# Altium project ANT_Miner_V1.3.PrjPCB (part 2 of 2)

## Sheet HashUnit3.SchDoc: ANT_Miner_V1.3
size A2; Date: 2013/11/20; DrawnBy: Bitmain Technology; SheetNumber: 8; SheetTotal: 9
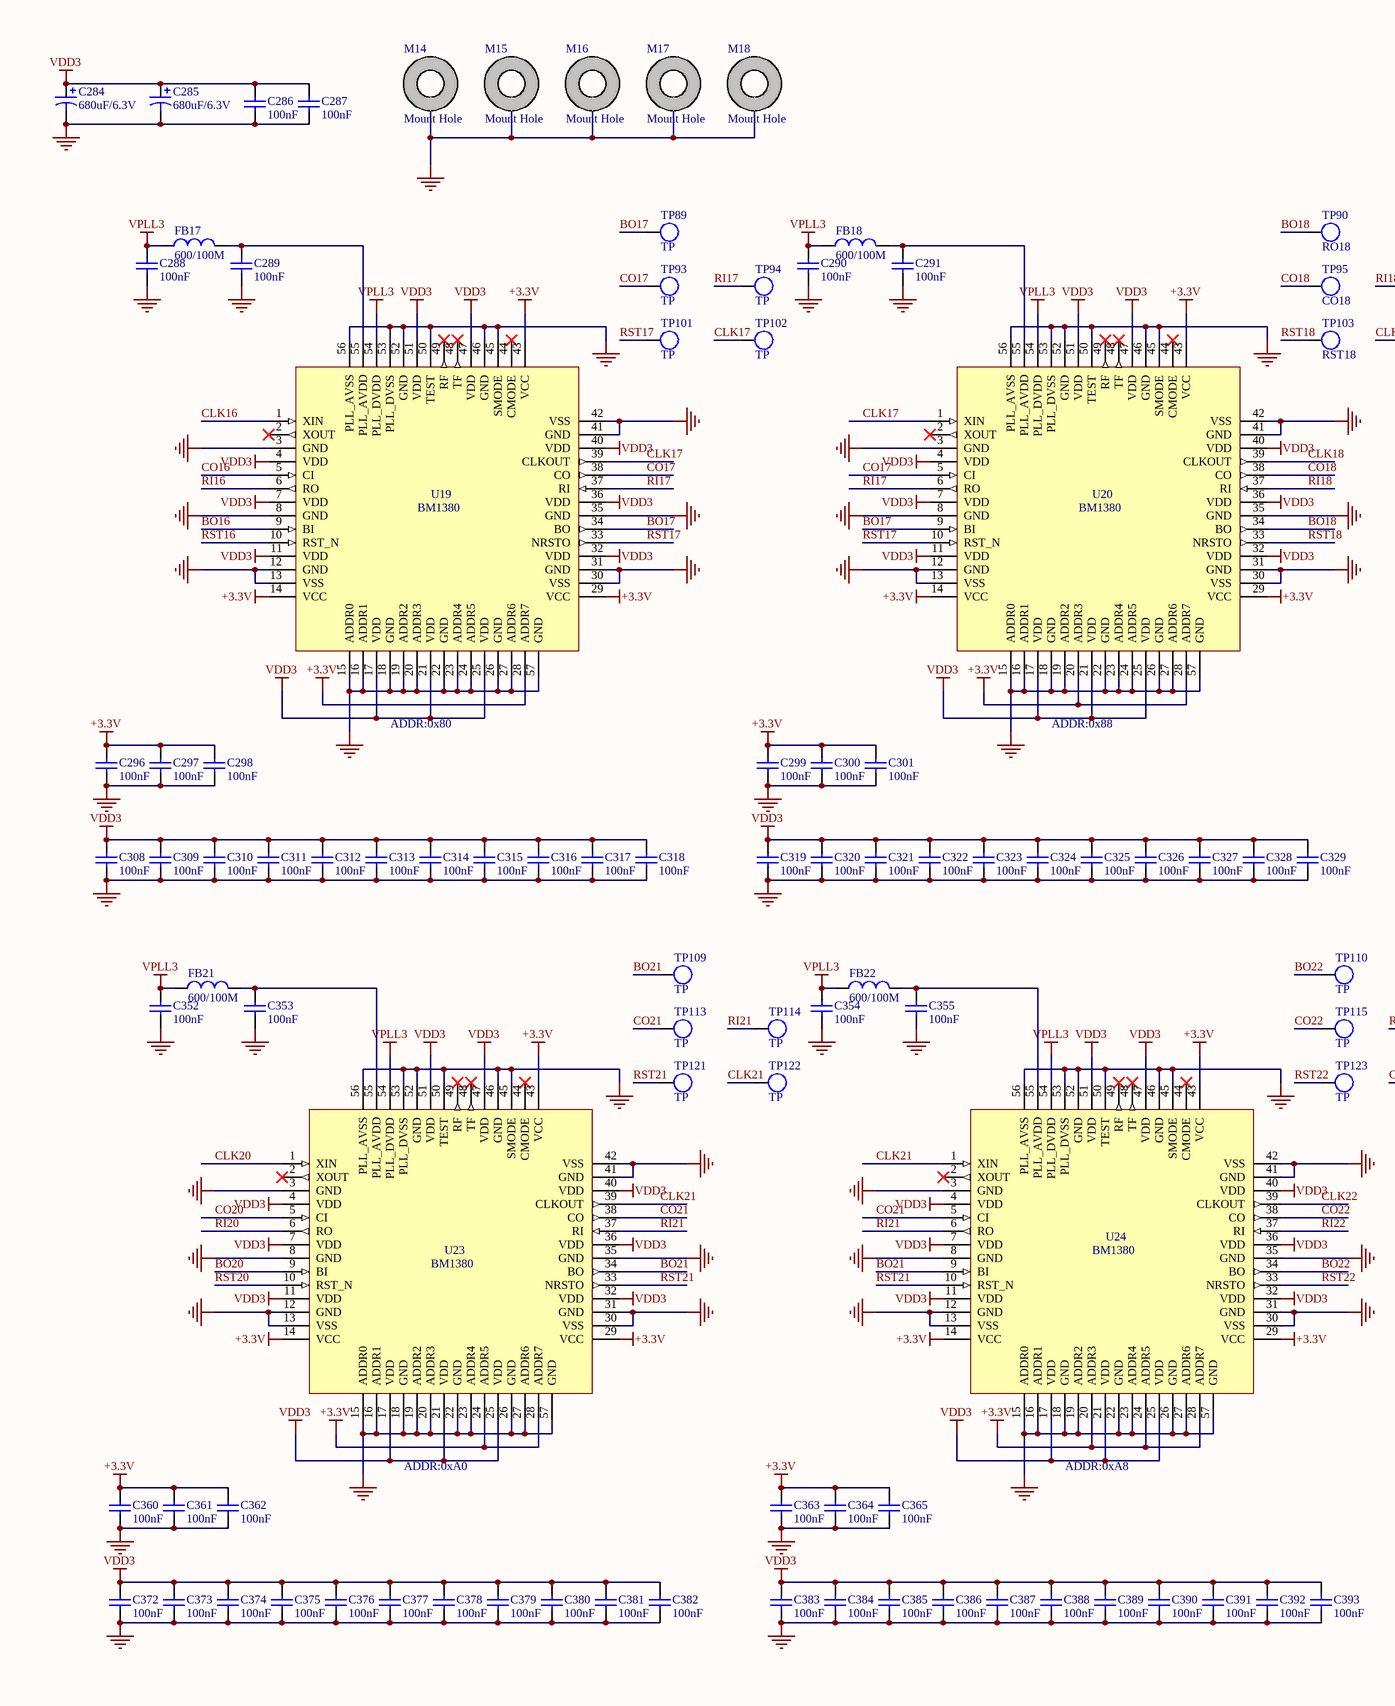
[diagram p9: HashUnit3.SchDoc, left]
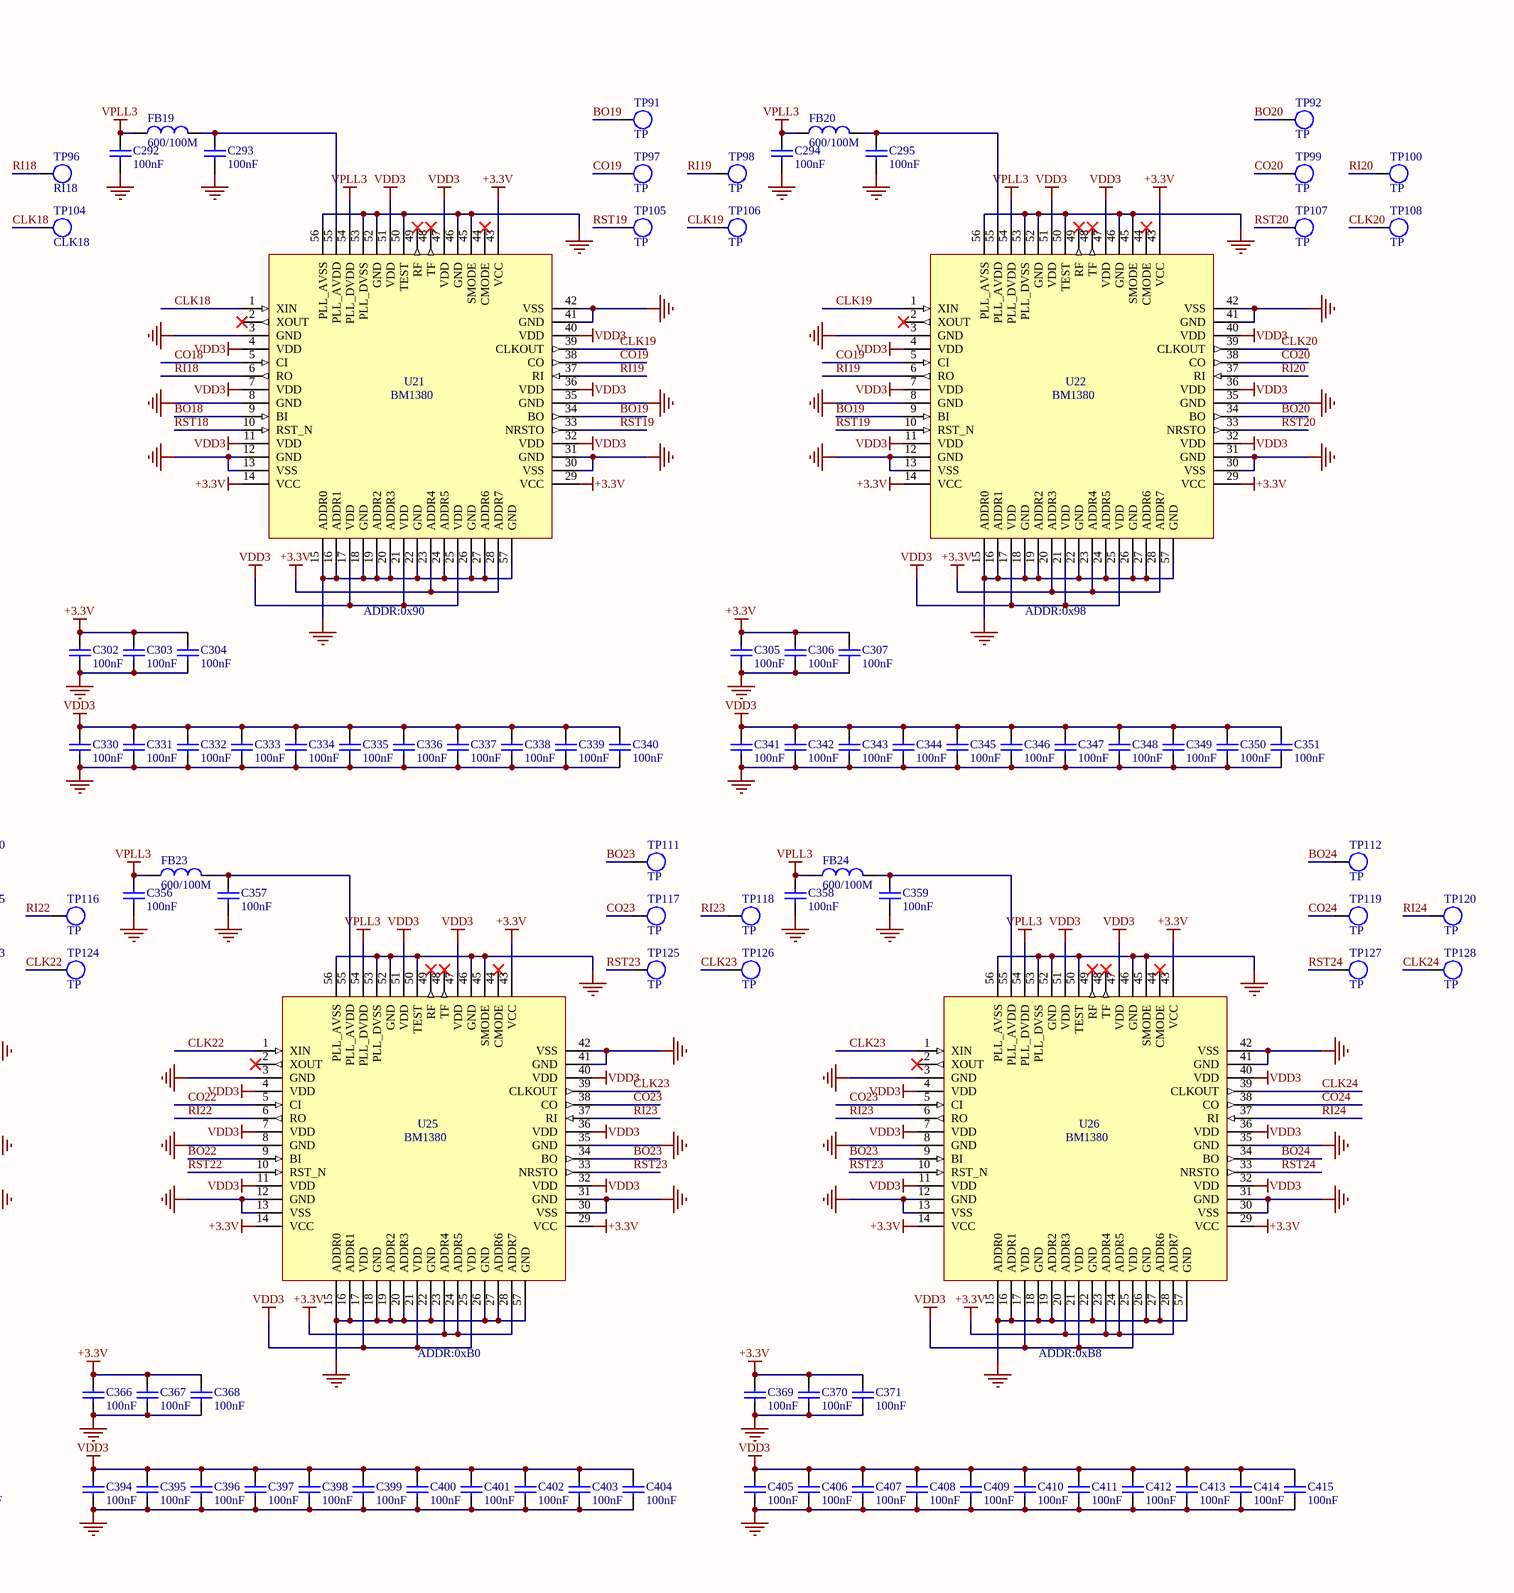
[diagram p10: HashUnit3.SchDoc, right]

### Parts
C284  680uF/6.3V  [D]
C285  680uF/6.3V  [D]
C286  100nF  [CC0603(1608)]
C287  100nF  [CC0603(1608)]
C288  100nF  [CC0603(1608)]
C289  100nF  [CC0603(1608)]
C290  100nF  [CC0603(1608)]
C291  100nF  [CC0603(1608)]
C292  100nF  [CC0603(1608)]
C293  100nF  [CC0603(1608)]
C294  100nF  [CC0603(1608)]
C295  100nF  [CC0603(1608)]
C296  100nF  [CC0603(1608)]
C297  100nF  [CC0603(1608)]
C298  100nF  [CC0603(1608)]
C299  100nF  [CC0603(1608)]
C300  100nF  [CC0603(1608)]
C301  100nF  [CC0603(1608)]
C302  100nF  [CC0603(1608)]
C303  100nF  [CC0603(1608)]
C304  100nF  [CC0603(1608)]
C305  100nF  [CC0603(1608)]
C306  100nF  [CC0603(1608)]
C307  100nF  [CC0603(1608)]
C308  100nF  [CC0603(1608)]
C309  100nF  [CC0603(1608)]
C310  100nF  [CC0603(1608)]
C311  100nF  [CC0603(1608)]
C312  100nF  [CC0603(1608)]
C313  100nF  [CC0603(1608)]
C314  100nF  [CC0603(1608)]
C315  100nF  [CC0603(1608)]
C316  100nF  [CC0603(1608)]
C317  100nF  [CC0603(1608)]
C318  100nF  [CC0603(1608)]
C319  100nF  [CC0603(1608)]
C320  100nF  [CC0603(1608)]
C321  100nF  [CC0603(1608)]
C322  100nF  [CC0603(1608)]
C323  100nF  [CC0603(1608)]
C324  100nF  [CC0603(1608)]
C325  100nF  [CC0603(1608)]
C326  100nF  [CC0603(1608)]
C327  100nF  [CC0603(1608)]
C328  100nF  [CC0603(1608)]
C329  100nF  [CC0603(1608)]
C330  100nF  [CC0603(1608)]
C331  100nF  [CC0603(1608)]
C332  100nF  [CC0603(1608)]
C333  100nF  [CC0603(1608)]
C334  100nF  [CC0603(1608)]
C335  100nF  [CC0603(1608)]
C336  100nF  [CC0603(1608)]
C337  100nF  [CC0603(1608)]
C338  100nF  [CC0603(1608)]
C339  100nF  [CC0603(1608)]
C340  100nF  [CC0603(1608)]
C341  100nF  [CC0603(1608)]
C342  100nF  [CC0603(1608)]
C343  100nF  [CC0603(1608)]
C344  100nF  [CC0603(1608)]
C345  100nF  [CC0603(1608)]
C346  100nF  [CC0603(1608)]
C347  100nF  [CC0603(1608)]
C348  100nF  [CC0603(1608)]
C349  100nF  [CC0603(1608)]
C350  100nF  [CC0603(1608)]
C351  100nF  [CC0603(1608)]
C352  100nF  [CC0603(1608)]
C353  100nF  [CC0603(1608)]
C354  100nF  [CC0603(1608)]
C355  100nF  [CC0603(1608)]
C356  100nF  [CC0603(1608)]
C357  100nF  [CC0603(1608)]
C358  100nF  [CC0603(1608)]
C359  100nF  [CC0603(1608)]
C360  100nF  [CC0603(1608)]
C361  100nF  [CC0603(1608)]
C362  100nF  [CC0603(1608)]
C363  100nF  [CC0603(1608)]
C364  100nF  [CC0603(1608)]
C365  100nF  [CC0603(1608)]
C366  100nF  [CC0603(1608)]
C367  100nF  [CC0603(1608)]
C368  100nF  [CC0603(1608)]
C369  100nF  [CC0603(1608)]
C370  100nF  [CC0603(1608)]
C371  100nF  [CC0603(1608)]
C372  100nF  [CC0603(1608)]
C373  100nF  [CC0603(1608)]
C374  100nF  [CC0603(1608)]
C375  100nF  [CC0603(1608)]
C376  100nF  [CC0603(1608)]
C377  100nF  [CC0603(1608)]
C378  100nF  [CC0603(1608)]
C379  100nF  [CC0603(1608)]
C380  100nF  [CC0603(1608)]
C381  100nF  [CC0603(1608)]
C382  100nF  [CC0603(1608)]
C383  100nF  [CC0603(1608)]
C384  100nF  [CC0603(1608)]
C385  100nF  [CC0603(1608)]
C386  100nF  [CC0603(1608)]
C387  100nF  [CC0603(1608)]
C388  100nF  [CC0603(1608)]
C389  100nF  [CC0603(1608)]
C390  100nF  [CC0603(1608)]
C391  100nF  [CC0603(1608)]
C392  100nF  [CC0603(1608)]
C393  100nF  [CC0603(1608)]
C394  100nF  [CC0603(1608)]
C395  100nF  [CC0603(1608)]
C396  100nF  [CC0603(1608)]
C397  100nF  [CC0603(1608)]
C398  100nF  [CC0603(1608)]
C399  100nF  [CC0603(1608)]
C400  100nF  [CC0603(1608)]
C401  100nF  [CC0603(1608)]
C402  100nF  [CC0603(1608)]
C403  100nF  [CC0603(1608)]
C404  100nF  [CC0603(1608)]
C405  100nF  [CC0603(1608)]
C406  100nF  [CC0603(1608)]
C407  100nF  [CC0603(1608)]
C408  100nF  [CC0603(1608)]
C409  100nF  [CC0603(1608)]
C410  100nF  [CC0603(1608)]
C411  100nF  [CC0603(1608)]
C412  100nF  [CC0603(1608)]
C413  100nF  [CC0603(1608)]
C414  100nF  [CC0603(1608)]
C415  100nF  [CC0603(1608)]
FB17  600/100M  [FB0603(1608)]
FB18  600/100M  [FB0603(1608)]
FB19  600/100M  [FB0603(1608)]
FB20  600/100M  [FB0603(1608)]
FB21  600/100M  [FB0603(1608)]
FB22  600/100M  [FB0603(1608)]
FB23  600/100M  [FB0603(1608)]
FB24  600/100M  [FB0603(1608)]
M14  Mount Hole  [MHOLE2]
M15  Mount Hole  [MHOLE2]
M16  Mount Hole  [MHOLE2]
M17  Mount Hole  [MHOLE2]
M18  Mount Hole  [MHOLE2]
TP89  TP  [TP_SMD]
TP90  value RO18  [TP_SMD]  (hidden comment: TP)
TP91  TP  [TP_SMD]
TP92  TP  [TP_SMD]
TP93  TP  [TP_SMD]
TP94  TP  [TP_SMD]
TP95  value CO18  [TP_SMD]  (hidden comment: TP)
TP96  value RI18  [TP_SMD]  (hidden comment: TP)
TP97  TP  [TP_SMD]
TP98  TP  [TP_SMD]
TP99  TP  [TP_SMD]
TP100  TP  [TP_SMD]
TP101  TP  [TP_SMD]
TP102  TP  [TP_SMD]
TP103  value RST18  [TP_SMD]  (hidden comment: TP)
TP104  value CLK18  [TP_SMD]  (hidden comment: TP)
TP105  TP  [TP_SMD]
TP106  TP  [TP_SMD]
TP107  TP  [TP_SMD]
TP108  TP  [TP_SMD]
TP109  TP  [TP_SMD]
TP110  TP  [TP_SMD]
TP111  TP  [TP_SMD]
TP112  TP  [TP_SMD]
TP113  TP  [TP_SMD]
TP114  TP  [TP_SMD]
TP115  TP  [TP_SMD]
TP116  TP  [TP_SMD]
TP117  TP  [TP_SMD]
TP118  TP  [TP_SMD]
TP119  TP  [TP_SMD]
TP120  TP  [TP_SMD]
TP121  TP  [TP_SMD]
TP122  TP  [TP_SMD]
TP123  TP  [TP_SMD]
TP124  TP  [TP_SMD]
TP125  TP  [TP_SMD]
TP126  TP  [TP_SMD]
TP127  TP  [TP_SMD]
TP128  TP  [TP_SMD]
U19  BM1380  [QFN56]
U20  BM1380  [QFN56]
U21  BM1380  [QFN56]
U22  BM1380  [QFN56]
U23  BM1380  [QFN56]
U24  BM1380  [QFN56]
U25  BM1380  [QFN56]
U26  BM1380  [QFN56]

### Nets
+3.3V: C296.2 C297.2 C298.2 C299.2 C300.2 C301.2 C302.2 C303.2 C304.2 C305.2 C306.2 C307.2 C360.2 C361.2 C362.2 C363.2 C364.2 C365.2 C366.2 C367.2 C368.2 C369.2 C370.2 C371.2 U19.14(VCC) U19.28(ADDR7) U19.29(VCC) U19.43(VCC) U20.14(VCC) U20.20(ADDR3) U20.28(ADDR7) U20.29(VCC) U20.43(VCC) U21.14(VCC) U21.23(ADDR4) U21.28(ADDR7) U21.29(VCC) U21.43(VCC) U22.14(VCC) U22.20(ADDR3) U22.23(ADDR4) U22.28(ADDR7) U22.29(VCC) U22.43(VCC) U23.14(VCC) U23.24(ADDR5) U23.28(ADDR7) U23.29(VCC) U23.43(VCC) U24.14(VCC) U24.20(ADDR3) U24.24(ADDR5) U24.28(ADDR7) U24.29(VCC) U24.43(VCC) U25.14(VCC) U25.23(ADDR4) U25.24(ADDR5) U25.28(ADDR7) U25.29(VCC) U25.43(VCC) U26.14(VCC) U26.20(ADDR3) U26.23(ADDR4) U26.24(ADDR5) U26.28(ADDR7) U26.29(VCC) U26.43(VCC)
GND: C284.2 C285.2 C286.1 C287.1 C288.2 C289.1 C290.2 C291.1 C292.2 C293.1 C294.2 C295.1 C296.1 C297.1 C298.1 C299.1 C300.1 C301.1 C302.1 C303.1 C304.1 C305.1 C306.1 C307.1 C308.1 C309.1 C310.1 C311.1 C312.1 C313.1 C314.1 C315.1 C316.1 C317.1 C318.1 C319.1 C320.1 C321.1 C322.1 C323.1 C324.1 C325.1 C326.1 C327.1 C328.1 C329.1 C330.1 C331.1 C332.1 C333.1 C334.1 C335.1 C336.1 C337.1 C338.1 C339.1 C340.1 C341.1 C342.1 C343.1 C344.1 C345.1 C346.1 C347.1 C348.1 C349.1 C350.1 C351.1 C352.2 C353.1 C354.2 C355.1 C356.2 C357.1 C358.2 C359.1 C360.1 C361.1 C362.1 C363.1 C364.1 C365.1 C366.1 C367.1 C368.1 C369.1 C370.1 C371.1 C372.1 C373.1 C374.1 C375.1 C376.1 C377.1 C378.1 C379.1 C380.1 C381.1 C382.1 C383.1 C384.1 C385.1 C386.1 C387.1 C388.1 C389.1 C390.1 C391.1 C392.1 C393.1 C394.1 C395.1 C396.1 C397.1 C398.1 C399.1 C400.1 C401.1 C402.1 C403.1 C404.1 C405.1 C406.1 C407.1 C408.1 C409.1 C410.1 C411.1 C412.1 C413.1 C414.1 C415.1 M14.0(PIN) M15.0(PIN) M16.0(PIN) M17.0(PIN) M18.0(PIN) U19.3(GND) U19.8(GND) U19.12(GND) U19.13(VSS) U19.15(ADDR0) U19.16(ADDR1) U19.18(GND) U19.19(ADDR2) U19.20(ADDR3) U19.22(GND) U19.23(ADDR4) U19.24(ADDR5) U19.26(GND) U19.27(ADDR6) U19.30(VSS) U19.31(GND) U19.35(GND) U19.41(GND) U19.42(VSS) U19.45(SMODE) U19.46(GND) U19.50(TEST) U19.52(GND) U19.53(PLL_DVSS) U19.56(PLL_AVSS) U19.57(GND) U20.3(GND) U20.8(GND) U20.12(GND) U20.13(VSS) U20.15(ADDR0) U20.16(ADDR1) U20.18(GND) U20.19(ADDR2) U20.22(GND) U20.23(ADDR4) U20.24(ADDR5) U20.26(GND) U20.27(ADDR6) U20.30(VSS) U20.31(GND) U20.35(GND) U20.41(GND) U20.42(VSS) U20.45(SMODE) U20.46(GND) U20.50(TEST) U20.52(GND) U20.53(PLL_DVSS) U20.56(PLL_AVSS) U20.57(GND) U21.3(GND) U21.8(GND) U21.12(GND) U21.13(VSS) U21.15(ADDR0) U21.16(ADDR1) U21.18(GND) U21.19(ADDR2) U21.20(ADDR3) U21.22(GND) U21.24(ADDR5) U21.26(GND) U21.27(ADDR6) U21.30(VSS) U21.31(GND) U21.35(GND) U21.41(GND) U21.42(VSS) U21.45(SMODE) U21.46(GND) U21.50(TEST) U21.52(GND) U21.53(PLL_DVSS) U21.56(PLL_AVSS) U21.57(GND) U22.3(GND) U22.8(GND) U22.12(GND) U22.13(VSS) U22.15(ADDR0) U22.16(ADDR1) U22.18(GND) U22.19(ADDR2) U22.22(GND) U22.24(ADDR5) U22.26(GND) U22.27(ADDR6) U22.30(VSS) U22.31(GND) U22.35(GND) U22.41(GND) U22.42(VSS) U22.45(SMODE) U22.46(GND) U22.50(TEST) U22.52(GND) U22.53(PLL_DVSS) U22.56(PLL_AVSS) U22.57(GND) U23.3(GND) U23.8(GND) U23.12(GND) U23.13(VSS) U23.15(ADDR0) U23.16(ADDR1) U23.18(GND) U23.19(ADDR2) U23.20(ADDR3) U23.22(GND) U23.23(ADDR4) U23.26(GND) U23.27(ADDR6) U23.30(VSS) U23.31(GND) U23.35(GND) U23.41(GND) U23.42(VSS) U23.45(SMODE) U23.46(GND) U23.50(TEST) U23.52(GND) U23.53(PLL_DVSS) U23.56(PLL_AVSS) U23.57(GND) U24.3(GND) U24.8(GND) U24.12(GND) U24.13(VSS) U24.15(ADDR0) U24.16(ADDR1) U24.18(GND) U24.19(ADDR2) U24.22(GND) U24.23(ADDR4) U24.26(GND) U24.27(ADDR6) U24.30(VSS) U24.31(GND) U24.35(GND) U24.41(GND) U24.42(VSS) U24.45(SMODE) U24.46(GND) U24.50(TEST) U24.52(GND) U24.53(PLL_DVSS) U24.56(PLL_AVSS) U24.57(GND) U25.3(GND) U25.8(GND) U25.12(GND) U25.13(VSS) U25.15(ADDR0) U25.16(ADDR1) U25.18(GND) U25.19(ADDR2) U25.20(ADDR3) U25.22(GND) U25.26(GND) U25.27(ADDR6) U25.30(VSS) U25.31(GND) U25.35(GND) U25.41(GND) U25.42(VSS) U25.45(SMODE) U25.46(GND) U25.50(TEST) U25.52(GND) U25.53(PLL_DVSS) U25.56(PLL_AVSS) U25.57(GND) U26.3(GND) U26.8(GND) U26.12(GND) U26.13(VSS) U26.15(ADDR0) U26.16(ADDR1) U26.18(GND) U26.19(ADDR2) U26.22(GND) U26.26(GND) U26.27(ADDR6) U26.30(VSS) U26.31(GND) U26.35(GND) U26.41(GND) U26.42(VSS) U26.45(SMODE) U26.46(GND) U26.50(TEST) U26.52(GND) U26.53(PLL_DVSS) U26.56(PLL_AVSS) U26.57(GND)
VDD3: C284.1 C285.1 C286.2 C287.2 C308.2 C309.2 C310.2 C311.2 C312.2 C313.2 C314.2 C315.2 C316.2 C317.2 C318.2 C319.2 C320.2 C321.2 C322.2 C323.2 C324.2 C325.2 C326.2 C327.2 C328.2 C329.2 C330.2 C331.2 C332.2 C333.2 C334.2 C335.2 C336.2 C337.2 C338.2 C339.2 C340.2 C341.2 C342.2 C343.2 C344.2 C345.2 C346.2 C347.2 C348.2 C349.2 C350.2 C351.2 C372.2 C373.2 C374.2 C375.2 C376.2 C377.2 C378.2 C379.2 C380.2 C381.2 C382.2 C383.2 C384.2 C385.2 C386.2 C387.2 C388.2 C389.2 C390.2 C391.2 C392.2 C393.2 C394.2 C395.2 C396.2 C397.2 C398.2 C399.2 C400.2 C401.2 C402.2 C403.2 C404.2 C405.2 C406.2 C407.2 C408.2 C409.2 C410.2 C411.2 C412.2 C413.2 C414.2 C415.2 U19.4(VDD) U19.7(VDD) U19.11(VDD) U19.17(VDD) U19.21(VDD) U19.25(VDD) U19.32(VDD) U19.36(VDD) U19.40(VDD) U19.47(VDD) U19.51(VDD) U20.4(VDD) U20.7(VDD) U20.11(VDD) U20.17(VDD) U20.21(VDD) U20.25(VDD) U20.32(VDD) U20.36(VDD) U20.40(VDD) U20.47(VDD) U20.51(VDD) U21.4(VDD) U21.7(VDD) U21.11(VDD) U21.17(VDD) U21.21(VDD) U21.25(VDD) U21.32(VDD) U21.36(VDD) U21.40(VDD) U21.47(VDD) U21.51(VDD) U22.4(VDD) U22.7(VDD) U22.11(VDD) U22.17(VDD) U22.21(VDD) U22.25(VDD) U22.32(VDD) U22.36(VDD) U22.40(VDD) U22.47(VDD) U22.51(VDD) U23.4(VDD) U23.7(VDD) U23.11(VDD) U23.17(VDD) U23.21(VDD) U23.25(VDD) U23.32(VDD) U23.36(VDD) U23.40(VDD) U23.47(VDD) U23.51(VDD) U24.4(VDD) U24.7(VDD) U24.11(VDD) U24.17(VDD) U24.21(VDD) U24.25(VDD) U24.32(VDD) U24.36(VDD) U24.40(VDD) U24.47(VDD) U24.51(VDD) U25.4(VDD) U25.7(VDD) U25.11(VDD) U25.17(VDD) U25.21(VDD) U25.25(VDD) U25.32(VDD) U25.36(VDD) U25.40(VDD) U25.47(VDD) U25.51(VDD) U26.4(VDD) U26.7(VDD) U26.11(VDD) U26.17(VDD) U26.21(VDD) U26.25(VDD) U26.32(VDD) U26.36(VDD) U26.40(VDD) U26.47(VDD) U26.51(VDD)
VPLL3: C288.1 C290.1 C292.1 C294.1 C352.1 C354.1 C356.1 C358.1 FB17.2 FB18.2 FB19.2 FB20.2 FB21.2 FB22.2 FB23.2 FB24.2 U19.54(PLL_DVDD) U20.54(PLL_DVDD) U21.54(PLL_DVDD) U22.54(PLL_DVDD) U23.54(PLL_DVDD) U24.54(PLL_DVDD) U25.54(PLL_DVDD) U26.54(PLL_DVDD)
BO16: U19.9(BI)
BO17: TP89.1 U19.34(BO) U20.9(BI)
BO18: TP90.1 U20.34(BO) U21.9(BI)
BO19: TP91.1 U21.34(BO) U22.9(BI)
BO20: TP92.1 U22.34(BO) U23.9(BI)
BO21: TP109.1 U23.34(BO) U24.9(BI)
BO22: TP110.1 U24.34(BO) U25.9(BI)
BO23: TP111.1 U25.34(BO) U26.9(BI)
BO24: TP112.1 U26.34(BO)
CLK16: U19.1(XIN)
CLK17: TP102.1 U19.39(CLKOUT) U20.1(XIN)
CLK18: TP104.1 U20.39(CLKOUT) U21.1(XIN)
CLK19: TP106.1 U21.39(CLKOUT) U22.1(XIN)
CLK20: TP108.1 U22.39(CLKOUT) U23.1(XIN)
CLK21: TP122.1 U23.39(CLKOUT) U24.1(XIN)
CLK22: TP124.1 U24.39(CLKOUT) U25.1(XIN)
CLK23: TP126.1 U25.39(CLKOUT) U26.1(XIN)
CLK24: TP128.1 U26.39(CLKOUT)
CO16: U19.5(CI)
CO17: TP93.1 U19.38(CO) U20.5(CI)
CO18: TP95.1 U20.38(CO) U21.5(CI)
CO19: TP97.1 U21.38(CO) U22.5(CI)
CO20: TP99.1 U22.38(CO) U23.5(CI)
CO21: TP113.1 U23.38(CO) U24.5(CI)
CO22: TP115.1 U24.38(CO) U25.5(CI)
CO23: TP117.1 U25.38(CO) U26.5(CI)
CO24: TP119.1 U26.38(CO)
RI16: U19.6(RO)
RI17: TP94.1 U19.37(RI) U20.6(RO)
RI18: TP96.1 U20.37(RI) U21.6(RO)
RI19: TP98.1 U21.37(RI) U22.6(RO)
RI20: TP100.1 U22.37(RI) U23.6(RO)
RI21: TP114.1 U23.37(RI) U24.6(RO)
RI22: TP116.1 U24.37(RI) U25.6(RO)
RI23: TP118.1 U25.37(RI) U26.6(RO)
RI24: TP120.1 U26.37(RI)
RST16: U19.10(RST_N)
RST17: TP101.1 U19.33(NRSTO) U20.10(RST_N)
RST18: TP103.1 U20.33(NRSTO) U21.10(RST_N)
RST19: TP105.1 U21.33(NRSTO) U22.10(RST_N)
RST20: TP107.1 U22.33(NRSTO) U23.10(RST_N)
RST21: TP121.1 U23.33(NRSTO) U24.10(RST_N)
RST22: TP123.1 U24.33(NRSTO) U25.10(RST_N)
RST23: TP125.1 U25.33(NRSTO) U26.10(RST_N)
RST24: TP127.1 U26.33(NRSTO)
NetC289_2: C289.2 FB17.1 U19.55(PLL_AVDD)
NetC291_2: C291.2 FB18.1 U20.55(PLL_AVDD)
NetC293_2: C293.2 FB19.1 U21.55(PLL_AVDD)
NetC295_2: C295.2 FB20.1 U22.55(PLL_AVDD)
NetC353_2: C353.2 FB21.1 U23.55(PLL_AVDD)
NetC355_2: C355.2 FB22.1 U24.55(PLL_AVDD)
NetC357_2: C357.2 FB23.1 U25.55(PLL_AVDD)
NetC359_2: C359.2 FB24.1 U26.55(PLL_AVDD)

Not connected (* = marked no-connect by the designer): U19 2(XOUT)* 44(CMODE)* 48(TF)* 49(RF)*; U20 2(XOUT)* 44(CMODE)* 48(TF)* 49(RF)*; U21 2(XOUT)* 44(CMODE)* 48(TF)* 49(RF)*; U22 2(XOUT)* 44(CMODE)* 48(TF)* 49(RF)*; U23 2(XOUT)* 44(CMODE)* 48(TF)* 49(RF)*; U24 2(XOUT)* 44(CMODE)* 48(TF)* 49(RF)*; U25 2(XOUT)* 44(CMODE)* 48(TF)* 49(RF)*; U26 2(XOUT)* 44(CMODE)* 48(TF)* 49(RF)*

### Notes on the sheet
- ADDR:0x80
- ADDR:0x88
- ADDR:0x90
- ADDR:0x98
- ADDR:0xA0
- ADDR:0xA8
- ADDR:0xB0
- ADDR:0xB8

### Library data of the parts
C284 C285 = T492C: Solid Tantalum Chip Capacitor, T492 Series - CWR11 Style Per Mil-PRF-55365/8
C286 C287 = Cap Semi: Capacitor (Semiconductor SIM Model)
C288-C415 = Cap: Capacitor
FB17-FB24 = FB: Inductor; Code_IEC: 1005
M14-M18 = M_Hole
TP89-TP128 = TP: Test Point

## Sheet HashUnit4.SchDoc: ANT_Miner_V1.3
size A2; Date: 2013/11/20; DrawnBy: Bitmain Technology; SheetNumber: 9; SheetTotal: 9
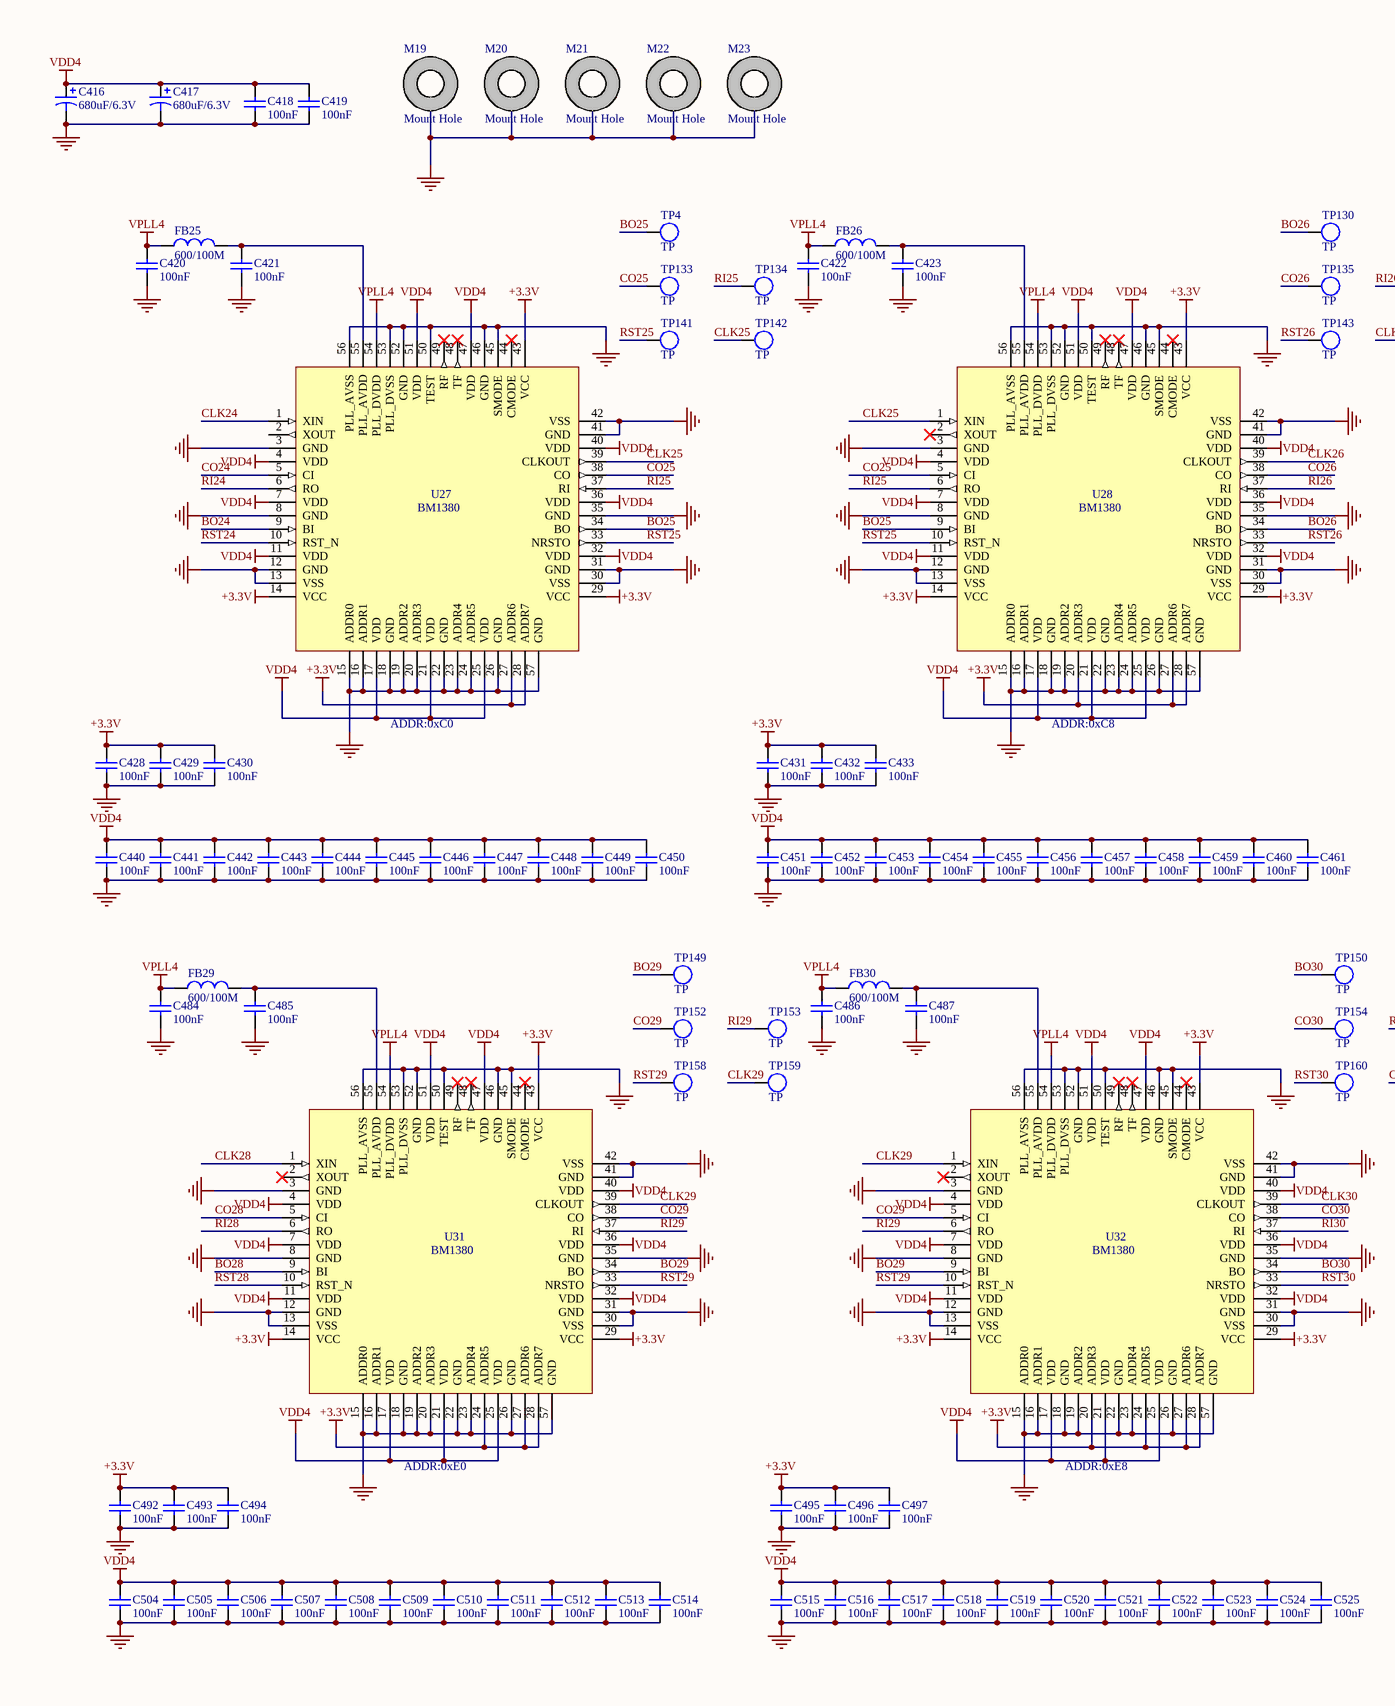
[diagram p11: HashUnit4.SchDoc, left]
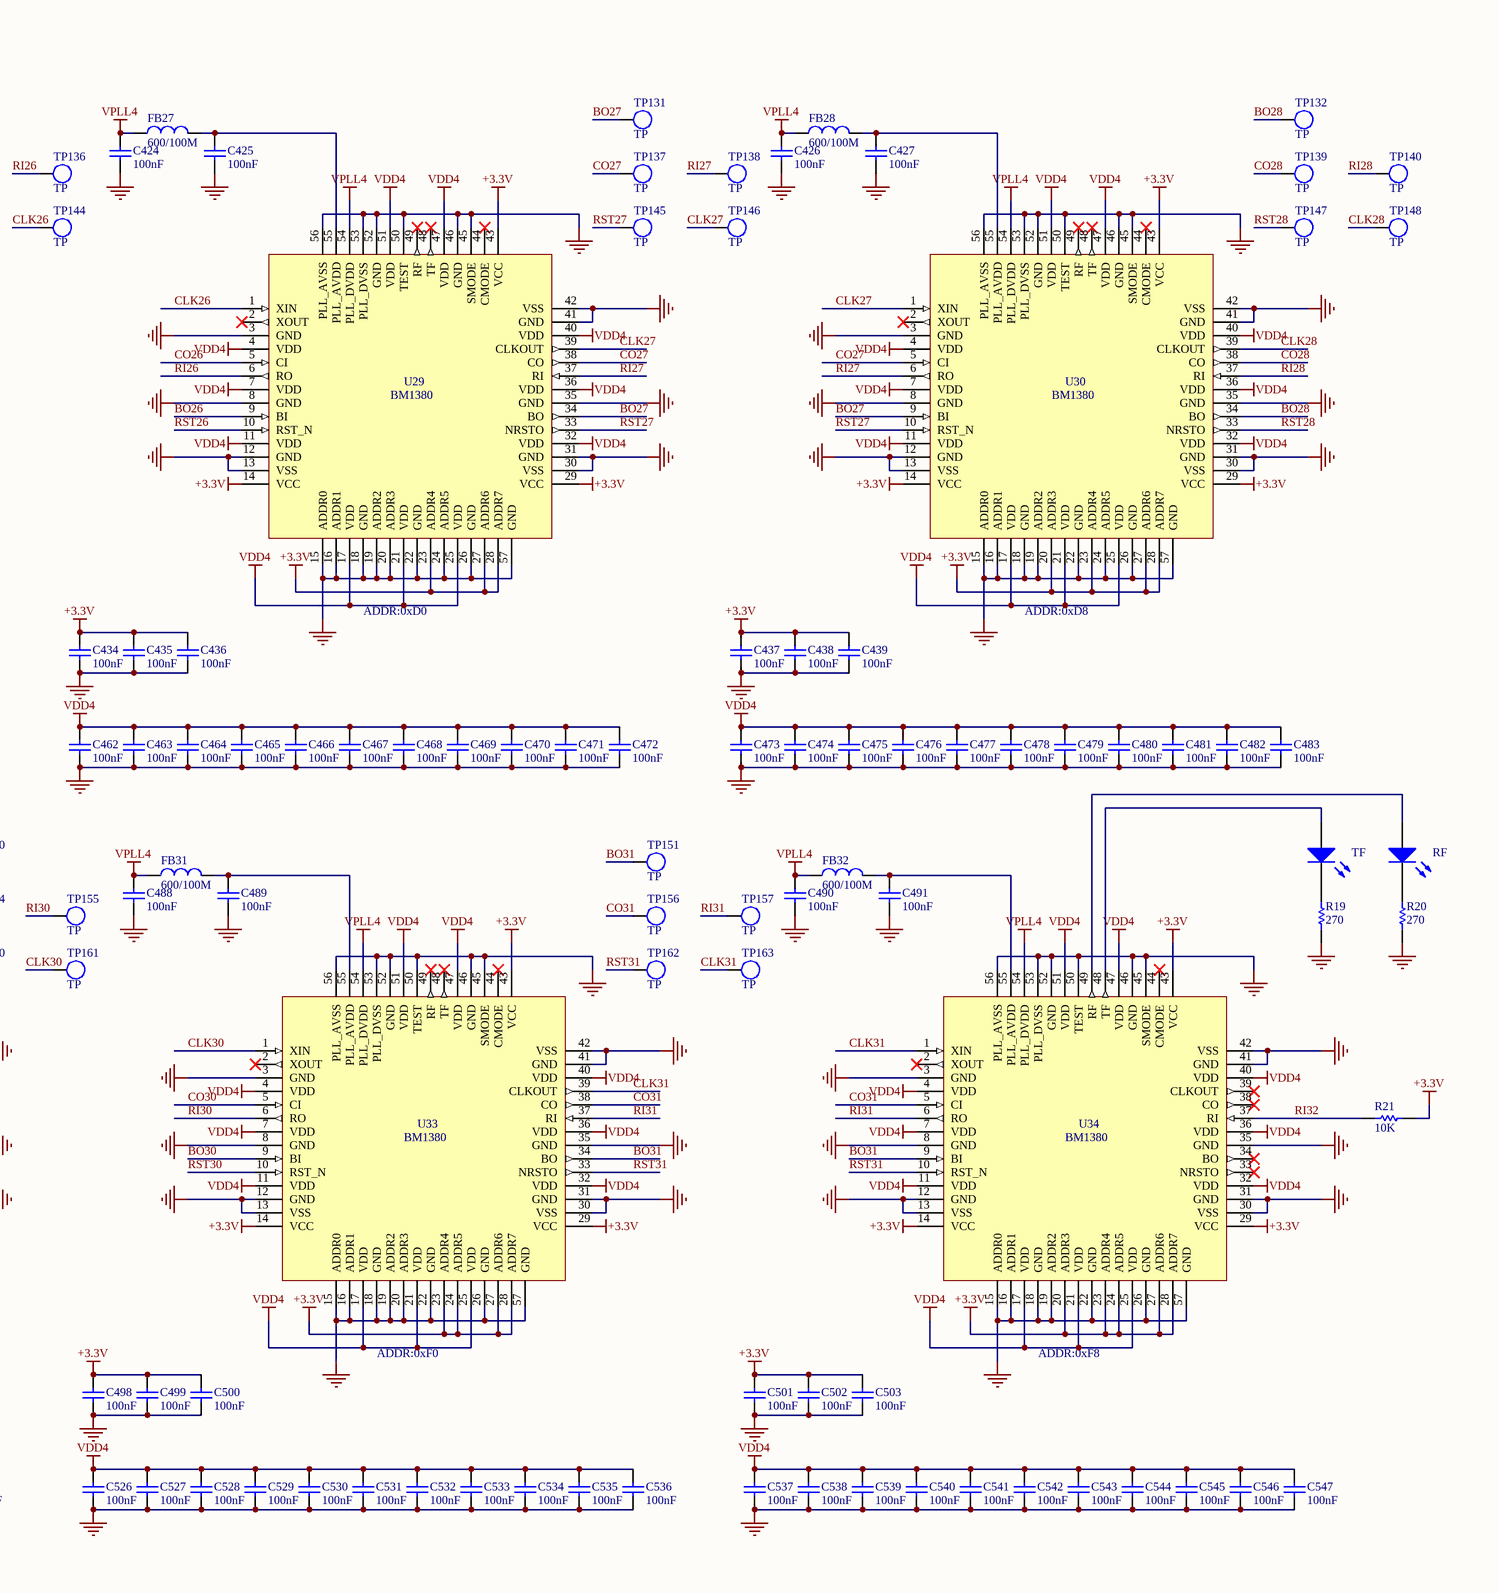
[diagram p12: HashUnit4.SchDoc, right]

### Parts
C416  680uF/6.3V  [D]
C417  680uF/6.3V  [D]
C418  100nF  [CC0603(1608)]
C419  100nF  [CC0603(1608)]
C420  100nF  [CC0603(1608)]
C421  100nF  [CC0603(1608)]
C422  100nF  [CC0603(1608)]
C423  100nF  [CC0603(1608)]
C424  100nF  [CC0603(1608)]
C425  100nF  [CC0603(1608)]
C426  100nF  [CC0603(1608)]
C427  100nF  [CC0603(1608)]
C428  100nF  [CC0603(1608)]
C429  100nF  [CC0603(1608)]
C430  100nF  [CC0603(1608)]
C431  100nF  [CC0603(1608)]
C432  100nF  [CC0603(1608)]
C433  100nF  [CC0603(1608)]
C434  100nF  [CC0603(1608)]
C435  100nF  [CC0603(1608)]
C436  100nF  [CC0603(1608)]
C437  100nF  [CC0603(1608)]
C438  100nF  [CC0603(1608)]
C439  100nF  [CC0603(1608)]
C440  100nF  [CC0603(1608)]
C441  100nF  [CC0603(1608)]
C442  100nF  [CC0603(1608)]
C443  100nF  [CC0603(1608)]
C444  100nF  [CC0603(1608)]
C445  100nF  [CC0603(1608)]
C446  100nF  [CC0603(1608)]
C447  100nF  [CC0603(1608)]
C448  100nF  [CC0603(1608)]
C449  100nF  [CC0603(1608)]
C450  100nF  [CC0603(1608)]
C451  100nF  [CC0603(1608)]
C452  100nF  [CC0603(1608)]
C453  100nF  [CC0603(1608)]
C454  100nF  [CC0603(1608)]
C455  100nF  [CC0603(1608)]
C456  100nF  [CC0603(1608)]
C457  100nF  [CC0603(1608)]
C458  100nF  [CC0603(1608)]
C459  100nF  [CC0603(1608)]
C460  100nF  [CC0603(1608)]
C461  100nF  [CC0603(1608)]
C462  100nF  [CC0603(1608)]
C463  100nF  [CC0603(1608)]
C464  100nF  [CC0603(1608)]
C465  100nF  [CC0603(1608)]
C466  100nF  [CC0603(1608)]
C467  100nF  [CC0603(1608)]
C468  100nF  [CC0603(1608)]
C469  100nF  [CC0603(1608)]
C470  100nF  [CC0603(1608)]
C471  100nF  [CC0603(1608)]
C472  100nF  [CC0603(1608)]
C473  100nF  [CC0603(1608)]
C474  100nF  [CC0603(1608)]
C475  100nF  [CC0603(1608)]
C476  100nF  [CC0603(1608)]
C477  100nF  [CC0603(1608)]
C478  100nF  [CC0603(1608)]
C479  100nF  [CC0603(1608)]
C480  100nF  [CC0603(1608)]
C481  100nF  [CC0603(1608)]
C482  100nF  [CC0603(1608)]
C483  100nF  [CC0603(1608)]
C484  100nF  [CC0603(1608)]
C485  100nF  [CC0603(1608)]
C486  100nF  [CC0603(1608)]
C487  100nF  [CC0603(1608)]
C488  100nF  [CC0603(1608)]
C489  100nF  [CC0603(1608)]
C490  100nF  [CC0603(1608)]
C491  100nF  [CC0603(1608)]
C492  100nF  [CC0603(1608)]
C493  100nF  [CC0603(1608)]
C494  100nF  [CC0603(1608)]
C495  100nF  [CC0603(1608)]
C496  100nF  [CC0603(1608)]
C497  100nF  [CC0603(1608)]
C498  100nF  [CC0603(1608)]
C499  100nF  [CC0603(1608)]
C500  100nF  [CC0603(1608)]
C501  100nF  [CC0603(1608)]
C502  100nF  [CC0603(1608)]
C503  100nF  [CC0603(1608)]
C504  100nF  [CC0603(1608)]
C505  100nF  [CC0603(1608)]
C506  100nF  [CC0603(1608)]
C507  100nF  [CC0603(1608)]
C508  100nF  [CC0603(1608)]
C509  100nF  [CC0603(1608)]
C510  100nF  [CC0603(1608)]
C511  100nF  [CC0603(1608)]
C512  100nF  [CC0603(1608)]
C513  100nF  [CC0603(1608)]
C514  100nF  [CC0603(1608)]
C515  100nF  [CC0603(1608)]
C516  100nF  [CC0603(1608)]
C517  100nF  [CC0603(1608)]
C518  100nF  [CC0603(1608)]
C519  100nF  [CC0603(1608)]
C520  100nF  [CC0603(1608)]
C521  100nF  [CC0603(1608)]
C522  100nF  [CC0603(1608)]
C523  100nF  [CC0603(1608)]
C524  100nF  [CC0603(1608)]
C525  100nF  [CC0603(1608)]
C526  100nF  [CC0603(1608)]
C527  100nF  [CC0603(1608)]
C528  100nF  [CC0603(1608)]
C529  100nF  [CC0603(1608)]
C530  100nF  [CC0603(1608)]
C531  100nF  [CC0603(1608)]
C532  100nF  [CC0603(1608)]
C533  100nF  [CC0603(1608)]
C534  100nF  [CC0603(1608)]
C535  100nF  [CC0603(1608)]
C536  100nF  [CC0603(1608)]
C537  100nF  [CC0603(1608)]
C538  100nF  [CC0603(1608)]
C539  100nF  [CC0603(1608)]
C540  100nF  [CC0603(1608)]
C541  100nF  [CC0603(1608)]
C542  100nF  [CC0603(1608)]
C543  100nF  [CC0603(1608)]
C544  100nF  [CC0603(1608)]
C545  100nF  [CC0603(1608)]
C546  100nF  [CC0603(1608)]
C547  100nF  [CC0603(1608)]
FB25  600/100M  [FB0603(1608)]
FB26  600/100M  [FB0603(1608)]
FB27  600/100M  [FB0603(1608)]
FB28  600/100M  [FB0603(1608)]
FB29  600/100M  [FB0603(1608)]
FB30  600/100M  [FB0603(1608)]
FB31  600/100M  [FB0603(1608)]
FB32  600/100M  [FB0603(1608)]
M19  Mount Hole  [MHOLE2]
M20  Mount Hole  [MHOLE2]
M21  Mount Hole  [MHOLE2]
M22  Mount Hole  [MHOLE2]
M23  Mount Hole  [MHOLE2]
R19  270  [RR0603(1608)]
R20  270  [RR0603(1608)]
R21  10K  [RR0603(1608)]
RF  Green  [LED0603(1608)]  (value not drawn)
TF  Green  [LED0603(1608)]  (value not drawn)
TP4  TP  [TP_SMD]
TP130  TP  [TP_SMD]
TP131  TP  [TP_SMD]
TP132  TP  [TP_SMD]
TP133  TP  [TP_SMD]
TP134  TP  [TP_SMD]
TP135  TP  [TP_SMD]
TP136  TP  [TP_SMD]
TP137  TP  [TP_SMD]
TP138  TP  [TP_SMD]
TP139  TP  [TP_SMD]
TP140  TP  [TP_SMD]
TP141  TP  [TP_SMD]
TP142  TP  [TP_SMD]
TP143  TP  [TP_SMD]
TP144  TP  [TP_SMD]
TP145  TP  [TP_SMD]
TP146  TP  [TP_SMD]
TP147  TP  [TP_SMD]
TP148  TP  [TP_SMD]
TP149  TP  [TP_SMD]
TP150  TP  [TP_SMD]
TP151  TP  [TP_SMD]
TP152  TP  [TP_SMD]
TP153  TP  [TP_SMD]
TP154  TP  [TP_SMD]
TP155  TP  [TP_SMD]
TP156  TP  [TP_SMD]
TP157  TP  [TP_SMD]
TP158  TP  [TP_SMD]
TP159  TP  [TP_SMD]
TP160  TP  [TP_SMD]
TP161  TP  [TP_SMD]
TP162  TP  [TP_SMD]
TP163  TP  [TP_SMD]
U27  BM1380  [QFN56]
U28  BM1380  [QFN56]
U29  BM1380  [QFN56]
U30  BM1380  [QFN56]
U31  BM1380  [QFN56]
U32  BM1380  [QFN56]
U33  BM1380  [QFN56]
U34  BM1380  [QFN56]

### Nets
+3.3V: C428.2 C429.2 C430.2 C431.2 C432.2 C433.2 C434.2 C435.2 C436.2 C437.2 C438.2 C439.2 C492.2 C493.2 C494.2 C495.2 C496.2 C497.2 C498.2 C499.2 C500.2 C501.2 C502.2 C503.2 R21.2 U27.14(VCC) U27.27(ADDR6) U27.28(ADDR7) U27.29(VCC) U27.43(VCC) U28.14(VCC) U28.20(ADDR3) U28.27(ADDR6) U28.28(ADDR7) U28.29(VCC) U28.43(VCC) U29.14(VCC) U29.23(ADDR4) U29.27(ADDR6) U29.28(ADDR7) U29.29(VCC) U29.43(VCC) U30.14(VCC) U30.20(ADDR3) U30.23(ADDR4) U30.27(ADDR6) U30.28(ADDR7) U30.29(VCC) U30.43(VCC) U31.14(VCC) U31.24(ADDR5) U31.27(ADDR6) U31.28(ADDR7) U31.29(VCC) U31.43(VCC) U32.14(VCC) U32.20(ADDR3) U32.24(ADDR5) U32.27(ADDR6) U32.28(ADDR7) U32.29(VCC) U32.43(VCC) U33.14(VCC) U33.23(ADDR4) U33.24(ADDR5) U33.27(ADDR6) U33.28(ADDR7) U33.29(VCC) U33.43(VCC) U34.14(VCC) U34.20(ADDR3) U34.23(ADDR4) U34.24(ADDR5) U34.27(ADDR6) U34.28(ADDR7) U34.29(VCC) U34.43(VCC)
GND: C416.2 C417.2 C418.1 C419.1 C420.2 C421.1 C422.2 C423.1 C424.2 C425.1 C426.2 C427.1 C428.1 C429.1 C430.1 C431.1 C432.1 C433.1 C434.1 C435.1 C436.1 C437.1 C438.1 C439.1 C440.1 C441.1 C442.1 C443.1 C444.1 C445.1 C446.1 C447.1 C448.1 C449.1 C450.1 C451.1 C452.1 C453.1 C454.1 C455.1 C456.1 C457.1 C458.1 C459.1 C460.1 C461.1 C462.1 C463.1 C464.1 C465.1 C466.1 C467.1 C468.1 C469.1 C470.1 C471.1 C472.1 C473.1 C474.1 C475.1 C476.1 C477.1 C478.1 C479.1 C480.1 C481.1 C482.1 C483.1 C484.2 C485.1 C486.2 C487.1 C488.2 C489.1 C490.2 C491.1 C492.1 C493.1 C494.1 C495.1 C496.1 C497.1 C498.1 C499.1 C500.1 C501.1 C502.1 C503.1 C504.1 C505.1 C506.1 C507.1 C508.1 C509.1 C510.1 C511.1 C512.1 C513.1 C514.1 C515.1 C516.1 C517.1 C518.1 C519.1 C520.1 C521.1 C522.1 C523.1 C524.1 C525.1 C526.1 C527.1 C528.1 C529.1 C530.1 C531.1 C532.1 C533.1 C534.1 C535.1 C536.1 C537.1 C538.1 C539.1 C540.1 C541.1 C542.1 C543.1 C544.1 C545.1 C546.1 C547.1 M19.0(PIN) M20.0(PIN) M21.0(PIN) M22.0(PIN) M23.0(PIN) R19.1 R20.1 U27.3(GND) U27.8(GND) U27.12(GND) U27.13(VSS) U27.15(ADDR0) U27.16(ADDR1) U27.18(GND) U27.19(ADDR2) U27.20(ADDR3) U27.22(GND) U27.23(ADDR4) U27.24(ADDR5) U27.26(GND) U27.30(VSS) U27.31(GND) U27.35(GND) U27.41(GND) U27.42(VSS) U27.45(SMODE) U27.46(GND) U27.50(TEST) U27.52(GND) U27.53(PLL_DVSS) U27.56(PLL_AVSS) U27.57(GND) U28.3(GND) U28.8(GND) U28.12(GND) U28.13(VSS) U28.15(ADDR0) U28.16(ADDR1) U28.18(GND) U28.19(ADDR2) U28.22(GND) U28.23(ADDR4) U28.24(ADDR5) U28.26(GND) U28.30(VSS) U28.31(GND) U28.35(GND) U28.41(GND) U28.42(VSS) U28.45(SMODE) U28.46(GND) U28.50(TEST) U28.52(GND) U28.53(PLL_DVSS) U28.56(PLL_AVSS) U28.57(GND) U29.3(GND) U29.8(GND) U29.12(GND) U29.13(VSS) U29.15(ADDR0) U29.16(ADDR1) U29.18(GND) U29.19(ADDR2) U29.20(ADDR3) U29.22(GND) U29.24(ADDR5) U29.26(GND) U29.30(VSS) U29.31(GND) U29.35(GND) U29.41(GND) U29.42(VSS) U29.45(SMODE) U29.46(GND) U29.50(TEST) U29.52(GND) U29.53(PLL_DVSS) U29.56(PLL_AVSS) U29.57(GND) U30.3(GND) U30.8(GND) U30.12(GND) U30.13(VSS) U30.15(ADDR0) U30.16(ADDR1) U30.18(GND) U30.19(ADDR2) U30.22(GND) U30.24(ADDR5) U30.26(GND) U30.30(VSS) U30.31(GND) U30.35(GND) U30.41(GND) U30.42(VSS) U30.45(SMODE) U30.46(GND) U30.50(TEST) U30.52(GND) U30.53(PLL_DVSS) U30.56(PLL_AVSS) U30.57(GND) U31.3(GND) U31.8(GND) U31.12(GND) U31.13(VSS) U31.15(ADDR0) U31.16(ADDR1) U31.18(GND) U31.19(ADDR2) U31.20(ADDR3) U31.22(GND) U31.23(ADDR4) U31.26(GND) U31.30(VSS) U31.31(GND) U31.35(GND) U31.41(GND) U31.42(VSS) U31.45(SMODE) U31.46(GND) U31.50(TEST) U31.52(GND) U31.53(PLL_DVSS) U31.56(PLL_AVSS) U31.57(GND) U32.3(GND) U32.8(GND) U32.12(GND) U32.13(VSS) U32.15(ADDR0) U32.16(ADDR1) U32.18(GND) U32.19(ADDR2) U32.22(GND) U32.23(ADDR4) U32.26(GND) U32.30(VSS) U32.31(GND) U32.35(GND) U32.41(GND) U32.42(VSS) U32.45(SMODE) U32.46(GND) U32.50(TEST) U32.52(GND) U32.53(PLL_DVSS) U32.56(PLL_AVSS) U32.57(GND) U33.3(GND) U33.8(GND) U33.12(GND) U33.13(VSS) U33.15(ADDR0) U33.16(ADDR1) U33.18(GND) U33.19(ADDR2) U33.20(ADDR3) U33.22(GND) U33.26(GND) U33.30(VSS) U33.31(GND) U33.35(GND) U33.41(GND) U33.42(VSS) U33.45(SMODE) U33.46(GND) U33.50(TEST) U33.52(GND) U33.53(PLL_DVSS) U33.56(PLL_AVSS) U33.57(GND) U34.3(GND) U34.8(GND) U34.12(GND) U34.13(VSS) U34.15(ADDR0) U34.16(ADDR1) U34.18(GND) U34.19(ADDR2) U34.22(GND) U34.26(GND) U34.30(VSS) U34.31(GND) U34.35(GND) U34.41(GND) U34.42(VSS) U34.45(SMODE) U34.46(GND) U34.50(TEST) U34.52(GND) U34.53(PLL_DVSS) U34.56(PLL_AVSS) U34.57(GND)
VDD4: C416.1 C417.1 C418.2 C419.2 C440.2 C441.2 C442.2 C443.2 C444.2 C445.2 C446.2 C447.2 C448.2 C449.2 C450.2 C451.2 C452.2 C453.2 C454.2 C455.2 C456.2 C457.2 C458.2 C459.2 C460.2 C461.2 C462.2 C463.2 C464.2 C465.2 C466.2 C467.2 C468.2 C469.2 C470.2 C471.2 C472.2 C473.2 C474.2 C475.2 C476.2 C477.2 C478.2 C479.2 C480.2 C481.2 C482.2 C483.2 C504.2 C505.2 C506.2 C507.2 C508.2 C509.2 C510.2 C511.2 C512.2 C513.2 C514.2 C515.2 C516.2 C517.2 C518.2 C519.2 C520.2 C521.2 C522.2 C523.2 C524.2 C525.2 C526.2 C527.2 C528.2 C529.2 C530.2 C531.2 C532.2 C533.2 C534.2 C535.2 C536.2 C537.2 C538.2 C539.2 C540.2 C541.2 C542.2 C543.2 C544.2 C545.2 C546.2 C547.2 U27.4(VDD) U27.7(VDD) U27.11(VDD) U27.17(VDD) U27.21(VDD) U27.25(VDD) U27.32(VDD) U27.36(VDD) U27.40(VDD) U27.47(VDD) U27.51(VDD) U28.4(VDD) U28.7(VDD) U28.11(VDD) U28.17(VDD) U28.21(VDD) U28.25(VDD) U28.32(VDD) U28.36(VDD) U28.40(VDD) U28.47(VDD) U28.51(VDD) U29.4(VDD) U29.7(VDD) U29.11(VDD) U29.17(VDD) U29.21(VDD) U29.25(VDD) U29.32(VDD) U29.36(VDD) U29.40(VDD) U29.47(VDD) U29.51(VDD) U30.4(VDD) U30.7(VDD) U30.11(VDD) U30.17(VDD) U30.21(VDD) U30.25(VDD) U30.32(VDD) U30.36(VDD) U30.40(VDD) U30.47(VDD) U30.51(VDD) U31.4(VDD) U31.7(VDD) U31.11(VDD) U31.17(VDD) U31.21(VDD) U31.25(VDD) U31.32(VDD) U31.36(VDD) U31.40(VDD) U31.47(VDD) U31.51(VDD) U32.4(VDD) U32.7(VDD) U32.11(VDD) U32.17(VDD) U32.21(VDD) U32.25(VDD) U32.32(VDD) U32.36(VDD) U32.40(VDD) U32.47(VDD) U32.51(VDD) U33.4(VDD) U33.7(VDD) U33.11(VDD) U33.17(VDD) U33.21(VDD) U33.25(VDD) U33.32(VDD) U33.36(VDD) U33.40(VDD) U33.47(VDD) U33.51(VDD) U34.4(VDD) U34.7(VDD) U34.11(VDD) U34.17(VDD) U34.21(VDD) U34.25(VDD) U34.32(VDD) U34.36(VDD) U34.40(VDD) U34.47(VDD) U34.51(VDD)
VPLL4: C420.1 C422.1 C424.1 C426.1 C484.1 C486.1 C488.1 C490.1 FB25.2 FB26.2 FB27.2 FB28.2 FB29.2 FB30.2 FB31.2 FB32.2 U27.54(PLL_DVDD) U28.54(PLL_DVDD) U29.54(PLL_DVDD) U30.54(PLL_DVDD) U31.54(PLL_DVDD) U32.54(PLL_DVDD) U33.54(PLL_DVDD) U34.54(PLL_DVDD)
BO24: U27.9(BI)
BO25: TP4.1 U27.34(BO) U28.9(BI)
BO26: TP130.1 U28.34(BO) U29.9(BI)
BO27: TP131.1 U29.34(BO) U30.9(BI)
BO28: TP132.1 U30.34(BO) U31.9(BI)
BO29: TP149.1 U31.34(BO) U32.9(BI)
BO30: TP150.1 U32.34(BO) U33.9(BI)
BO31: TP151.1 U33.34(BO) U34.9(BI)
CLK24: U27.1(XIN)
CLK25: TP142.1 U27.39(CLKOUT) U28.1(XIN)
CLK26: TP144.1 U28.39(CLKOUT) U29.1(XIN)
CLK27: TP146.1 U29.39(CLKOUT) U30.1(XIN)
CLK28: TP148.1 U30.39(CLKOUT) U31.1(XIN)
CLK29: TP159.1 U31.39(CLKOUT) U32.1(XIN)
CLK30: TP161.1 U32.39(CLKOUT) U33.1(XIN)
CLK31: TP163.1 U33.39(CLKOUT) U34.1(XIN)
CO24: U27.5(CI)
CO25: TP133.1 U27.38(CO) U28.5(CI)
CO26: TP135.1 U28.38(CO) U29.5(CI)
CO27: TP137.1 U29.38(CO) U30.5(CI)
CO28: TP139.1 U30.38(CO) U31.5(CI)
CO29: TP152.1 U31.38(CO) U32.5(CI)
CO30: TP154.1 U32.38(CO) U33.5(CI)
CO31: TP156.1 U33.38(CO) U34.5(CI)
RI24: U27.6(RO)
RI25: TP134.1 U27.37(RI) U28.6(RO)
RI26: TP136.1 U28.37(RI) U29.6(RO)
RI27: TP138.1 U29.37(RI) U30.6(RO)
RI28: TP140.1 U30.37(RI) U31.6(RO)
RI29: TP153.1 U31.37(RI) U32.6(RO)
RI30: TP155.1 U32.37(RI) U33.6(RO)
RI31: TP157.1 U33.37(RI) U34.6(RO)
RI32: R21.1 U34.37(RI)
RST24: U27.10(RST_N)
RST25: TP141.1 U27.33(NRSTO) U28.10(RST_N)
RST26: TP143.1 U28.33(NRSTO) U29.10(RST_N)
RST27: TP145.1 U29.33(NRSTO) U30.10(RST_N)
RST28: TP147.1 U30.33(NRSTO) U31.10(RST_N)
RST29: TP158.1 U31.33(NRSTO) U32.10(RST_N)
RST30: TP160.1 U32.33(NRSTO) U33.10(RST_N)
RST31: TP162.1 U33.33(NRSTO) U34.10(RST_N)
NetC421_2: C421.2 FB25.1 U27.55(PLL_AVDD)
NetC423_2: C423.2 FB26.1 U28.55(PLL_AVDD)
NetC425_2: C425.2 FB27.1 U29.55(PLL_AVDD)
NetC427_2: C427.2 FB28.1 U30.55(PLL_AVDD)
NetC485_2: C485.2 FB29.1 U31.55(PLL_AVDD)
NetC487_2: C487.2 FB30.1 U32.55(PLL_AVDD)
NetC489_2: C489.2 FB31.1 U33.55(PLL_AVDD)
NetC491_2: C491.2 FB32.1 U34.55(PLL_AVDD)
NetR19_2: R19.2 TF.2(K)
NetR20_2: R20.2 RF.2(K)
NetRF_1: RF.1(A) U34.49(RF)
NetTF_1: TF.1(A) U34.48(TF)

Not connected (* = marked no-connect by the designer): U27 2(XOUT) 44(CMODE)* 48(TF)* 49(RF)*; U28 2(XOUT)* 44(CMODE)* 48(TF)* 49(RF)*; U29 2(XOUT)* 44(CMODE)* 48(TF)* 49(RF)*; U30 2(XOUT)* 44(CMODE)* 48(TF)* 49(RF)*; U31 2(XOUT)* 44(CMODE)* 48(TF)* 49(RF)*; U32 2(XOUT)* 44(CMODE)* 48(TF)* 49(RF)*; U33 2(XOUT)* 44(CMODE)* 48(TF)* 49(RF)*; U34 2(XOUT)* 33(NRSTO)* 34(BO)* 38(CO)* 39(CLKOUT)* 44(CMODE)*

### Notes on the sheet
- ADDR:0xC0
- ADDR:0xC8
- ADDR:0xD0
- ADDR:0xD8
- ADDR:0xE0
- ADDR:0xE8
- ADDR:0xF0
- ADDR:0xF8

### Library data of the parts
C416 C417 = T492C: as C284 on sheet HashUnit3
C418 C419 = Cap Semi: Capacitor (Semiconductor SIM Model)
C420-C547 = Cap: Capacitor
FB25-FB32 = FB: Inductor; Code_IEC: 1005
M19-M23 = M_Hole
R19-R21 = Res1: Resistor
RF TF = LED0: Typical INFRARED GaAs LED
TP4 TP130-TP163 = TP: Test Point

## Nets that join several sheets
+3.3V: TOP (9 pins), HashPower1 (5 pins), HashPower2 (5 pins), HashPower3 (5 pins), HashPower4 (5 pins), HashUnit1 (62 pins), HashUnit2 (68 pins), HashUnit3 (68 pins), HashUnit4 (77 pins)
+12V: TOP (8 pins), HashPower1 (13 pins), HashPower2 (13 pins), HashPower3 (12 pins), HashPower4 (13 pins)
GND: TOP (25 pins), HashPower1 (23 pins), HashPower2 (23 pins), HashPower3 (23 pins), HashPower4 (23 pins), HashUnit1 (345 pins), HashUnit2 (333 pins), HashUnit3 (333 pins), HashUnit4 (327 pins)
VDD1: HashPower1 (9 pins), HashUnit1 (180 pins)
VDD2: HashPower2 (9 pins), HashUnit2 (180 pins)
VDD3: HashPower3 (8 pins), HashUnit3 (180 pins)
VDD4: HashPower4 (9 pins), HashUnit4 (180 pins)
VPLL1: HashPower1 (C16.2 R13.2 TP167.1 U2.5), HashUnit1 (24 pins)
VPLL2: HashPower2 (C563.2 R34.2 TP129.1 U36.5), HashUnit2 (24 pins)
VPLL3: HashPower3 (C579.2 R48.2 TP171.1 U38.5), HashUnit3 (24 pins)
VPLL4: HashPower4 (C595.2 R62.2 TP175.1 U40.5), HashUnit4 (24 pins)
BO8: HashUnit1 (TP32.1 U10.34), HashUnit2 (U11.9)
BO16: HashUnit2 (TP69.1 U18.34), HashUnit3 (U19.9)
BO24: HashUnit3 (TP112.1 U26.34), HashUnit4 (U27.9)
CLK8: HashUnit1 (TP48.1 U10.39), HashUnit2 (U11.1)
CLK16: HashUnit2 (TP82.1 U18.39), HashUnit3 (U19.1)
CLK24: HashUnit3 (TP128.1 U26.39), HashUnit4 (U27.1)
CO8: HashUnit1 (TP39.1 U10.38), HashUnit2 (U11.5)
CO16: HashUnit2 (TP73.1 U18.38), HashUnit3 (U19.5)
CO24: HashUnit3 (TP119.1 U26.38), HashUnit4 (U27.5)
RI8: HashUnit1 (TP40.1 U10.37), HashUnit2 (U11.6)
RI16: HashUnit2 (TP74.1 U18.37), HashUnit3 (U19.6)
RI24: HashUnit3 (TP120.1 U26.37), HashUnit4 (U27.6)
RST8: HashUnit1 (TP47.1 U10.33), HashUnit2 (U11.10)
RST16: HashUnit2 (TP81.1 U18.33), HashUnit3 (U19.10)
RST24: HashUnit3 (TP127.1 U26.33), HashUnit4 (U27.10)
RXD: TOP (J1.3), HashUnit1 (TP27.1 U3.6)
TXD: TOP (J1.5), HashUnit1 (R15.2 TP26.1 U3.5)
